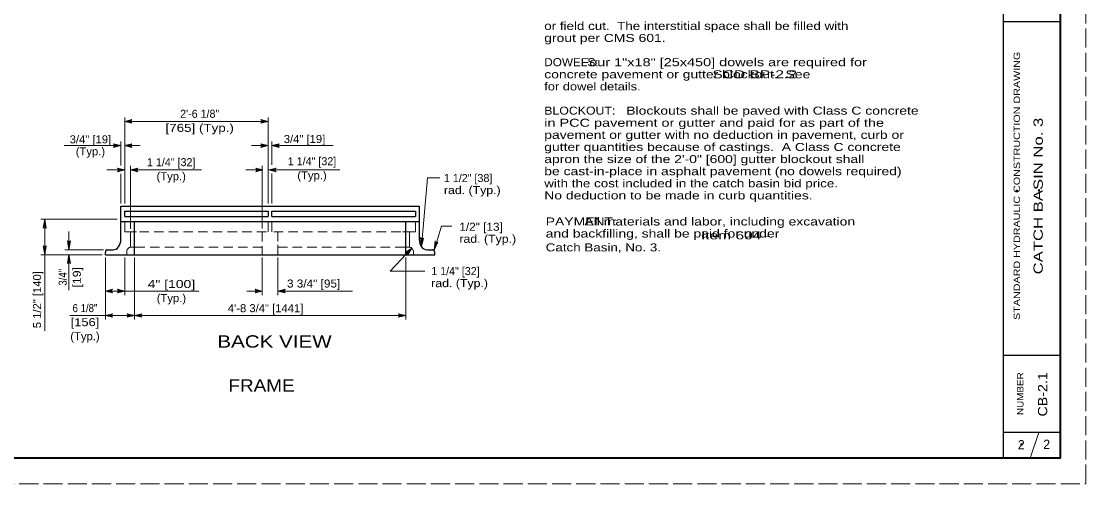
# Model space of a CAD drawing. Extents: x 1352.5 to 1386.5, y 735.9 to 779.9.
# Drawn here: x 1365.77 to 1386.51, y 735.92 to 744.93 of the extents above; entities that cross this region are included whole.
import ezdxf
from ezdxf.enums import TextEntityAlignment as Align

# ---------------------------------------------------------------- set-up
doc = ezdxf.new("R2010")
doc.units = 0
doc.header["$LTSCALE"] = 0.062
doc.header["$PDMODE"] = 32
doc.header["$PDSIZE"] = 0.031
doc.linetypes.add('LONG_DASHED', pattern=[7.5, 6, -1.5])
doc.linetypes.add('MEDIUM_DASHED', pattern=[4.5, 3, -1.5])
doc.layers.add('1', color=7, linetype='Continuous', lineweight=13)

msp = doc.modelspace()

# ---------------------------------------------------------------- linework, layer by layer
at = {"layer": '1', "lineweight": 25}
for p, q in [((1384.913, 736.41967), (1384.913, 757.41967)), ((1386.013, 757.41967), (1386.013, 736.41967)), ((1386.013, 744.91967), (1384.913, 744.91967)), ((1367.78425, 741.12625), (1367.78425, 741.22617)), ((1367.78425, 741.22617), (1370.5785, 741.22617)), ((1370.5785, 741.22617), (1370.5785, 741.12625)), ((1370.654, 741.22617), (1373.44825, 741.22617)), ((1370.654, 741.12625), (1370.654, 741.22617)), ((1373.44825, 741.22617), (1373.44825, 741.12625)), ((1367.70875, 741.02633), (1373.52375, 741.02633)), ((1367.78425, 741.12625), (1370.5785, 741.12625)), ((1367.973, 740.37667), (1367.973, 741.02633)), ((1370.654, 741.12625), (1373.44825, 741.12625)), ((1373.25942, 740.37667), (1373.25942, 741.02633)), ((1367.40667, 740.37667), (1367.40667, 740.42667)), ((1367.44442, 740.47667), (1367.55767, 740.47667)), ((1373.67475, 740.47667), (1373.78808, 740.47667)), ((1373.82583, 740.37667), (1373.82583, 740.42667)), ((1367.40667, 740.37667), (1373.82583, 740.37667)), ((1386.013, 738.41967), (1384.913, 738.41967)), ((1386.013, 736.91967), (1384.913, 736.91967))]:
    msp.add_line(p, q, dxfattribs=at)
at = {"layer": '1'}
for p, q in [((1367.78425, 741.37608), (1367.78425, 743.05675)), ((1367.91242, 743.0005), (1367.78425, 742.97808)), ((1367.90808, 742.98942), (1367.78425, 742.97808)), ((1367.78425, 742.97808), (1370.5785, 742.97808)), ((1367.90675, 742.97808), (1367.78425, 742.97808)), ((1367.909, 742.96367), (1367.78425, 742.97808)), ((1367.91392, 742.95333), (1367.78425, 742.97808)), ((1370.44875, 742.95333), (1370.5785, 742.97808)), ((1370.45025, 743.0005), (1370.5785, 742.97808)), ((1370.45367, 742.96367), (1370.5785, 742.97808)), ((1370.45458, 742.98942), (1370.5785, 742.97808)), ((1370.45592, 742.97808), (1370.5785, 742.97808)), ((1370.5785, 741.37608), (1370.5785, 743.05675)), ((1367.70658, 742.50733), (1366.60142, 742.50733)), ((1367.57692, 742.48258), (1367.70658, 742.50733)), ((1367.57842, 742.52975), (1367.70658, 742.50733)), ((1367.58183, 742.493), (1367.70658, 742.50733)), ((1367.58275, 742.51867), (1367.70658, 742.50733)), ((1367.58408, 742.50733), (1367.70658, 742.50733)), ((1367.70875, 742.11583), (1367.70875, 742.586)), ((1367.91033, 742.52975), (1367.78217, 742.50733)), ((1367.906, 742.51867), (1367.78217, 742.50733)), ((1367.90467, 742.50733), (1367.78217, 742.50733)), ((1367.90692, 742.493), (1367.78217, 742.50733)), ((1367.91183, 742.48258), (1367.78217, 742.50733)), ((1367.78217, 742.50733), (1368.08525, 742.50733)), ((1370.57858, 742.50733), (1370.25658, 742.50733)), ((1370.44892, 742.48258), (1370.57858, 742.50733)), ((1370.45042, 742.52975), (1370.57858, 742.50733)), ((1370.45383, 742.493), (1370.57858, 742.50733)), ((1370.45475, 742.51867), (1370.57858, 742.50733)), ((1370.45608, 742.50733), (1370.57858, 742.50733)), ((1370.654, 742.1345), (1370.654, 742.586)), ((1370.78233, 742.52975), (1370.65408, 742.50733)), ((1370.778, 742.51867), (1370.65408, 742.50733)), ((1370.65408, 742.50733), (1371.84508, 742.50733)), ((1370.77667, 742.50733), (1370.65408, 742.50733)), ((1370.77892, 742.493), (1370.65408, 742.50733)), ((1370.78383, 742.48258), (1370.65408, 742.50733)), ((1367.656, 742.05442), (1367.78425, 742.032)), ((1367.66042, 742.04333), (1367.78425, 742.032)), ((1367.8975, 740.88758), (1367.8975, 742.11067)), ((1368.02567, 742.05442), (1367.8975, 742.032)), ((1368.02133, 742.04333), (1367.8975, 742.032)), ((1370.34967, 742.05442), (1370.47783, 742.032)), ((1370.354, 742.04333), (1370.47783, 742.032)), ((1370.46517, 740.89475), (1370.46517, 742.11067)), ((1370.71933, 742.05442), (1370.59117, 742.032)), ((1370.715, 742.04333), (1370.59117, 742.032)), ((1367.78425, 742.032), (1367.43425, 742.032)), ((1367.6545, 742.00717), (1367.78425, 742.032)), ((1367.65942, 742.01758), (1367.78425, 742.032)), ((1367.66167, 742.032), (1367.78425, 742.032)), ((1367.70875, 741.37608), (1367.70875, 741.95742)), ((1368.02008, 742.032), (1367.8975, 742.032)), ((1368.02233, 742.01758), (1367.8975, 742.032)), ((1368.02725, 742.00717), (1367.8975, 742.032)), ((1367.8975, 742.032), (1369.27792, 742.032)), ((1370.47783, 742.032), (1370.14525, 742.032)), ((1370.34817, 742.00717), (1370.47783, 742.032)), ((1370.35308, 742.01758), (1370.47783, 742.032)), ((1370.35533, 742.032), (1370.47783, 742.032)), ((1370.71367, 742.032), (1370.59117, 742.032)), ((1370.71592, 742.01758), (1370.59117, 742.032)), ((1370.72083, 742.00717), (1370.59117, 742.032)), ((1370.59117, 742.032), (1371.97675, 742.032)), ((1370.654, 741.37608), (1370.654, 741.96208)), ((1366.20492, 740.91417), (1366.22475, 741.07625)), ((1366.21325, 740.92025), (1366.22475, 741.07625)), ((1366.22475, 740.92308), (1366.22475, 741.07625)), ((1366.23383, 740.9215), (1366.22475, 741.07625)), ((1366.24267, 740.91608), (1366.22475, 741.07625)), ((1367.78425, 741.02633), (1367.78425, 740.82642)), ((1373.44825, 741.02633), (1373.44825, 740.82642)), ((1366.69683, 740.47667), (1366.69683, 740.8345)), ((1367.78425, 740.82642), (1368.01508, 740.82642)), ((1367.8975, 740.82642), (1367.8975, 740.52658)), ((1373.44825, 740.82642), (1373.19692, 740.82642)), ((1373.33492, 740.82642), (1373.33492, 740.52658)), ((1366.67892, 740.63683), (1366.69683, 740.47667)), ((1366.68775, 740.63142), (1366.69683, 740.47667)), ((1366.71667, 740.63875), (1366.69683, 740.47667)), ((1366.70833, 740.63258), (1366.69683, 740.47667)), ((1366.69683, 740.62975), (1366.69683, 740.47667)), ((1373.56075, 740.70067), (1373.5695, 740.54117)), ((1373.56942, 740.6935), (1373.5695, 740.54117)), ((1373.59925, 740.69392), (1373.5695, 740.54117)), ((1373.59042, 740.68983), (1373.5695, 740.54117)), ((1373.5785, 740.68975), (1373.5695, 740.54117)), ((1373.84117, 740.62942), (1373.81217, 740.47092)), ((1373.84792, 740.62067), (1373.81217, 740.47092)), ((1373.877, 740.61567), (1373.81217, 740.47092)), ((1373.85592, 740.61533), (1373.81217, 740.47092)), ((1373.8675, 740.61325), (1373.81217, 740.47092)), ((1366.20683, 740.53692), (1366.22475, 740.37667)), ((1366.21567, 740.5315), (1366.22475, 740.37667)), ((1366.24458, 740.53883), (1366.22475, 740.37667)), ((1366.23625, 740.53267), (1366.22475, 740.37667)), ((1366.22475, 740.52983), (1366.22475, 740.37667)), ((1367.36883, 740.47667), (1366.61817, 740.47667)), ((1366.67892, 740.22633), (1366.69683, 740.38658)), ((1366.68775, 740.23175), (1366.69683, 740.38658)), ((1366.69683, 740.38658), (1366.69683, 739.69017)), ((1366.69683, 740.23342), (1366.69683, 740.38658)), ((1366.70833, 740.23058), (1366.69683, 740.38658)), ((1366.71667, 740.22442), (1366.69683, 740.38658)), ((1367.8975, 740.52658), (1368.01808, 740.52658)), ((1373.375, 740.50408), (1372.95808, 740.0575)), ((1373.33492, 740.52658), (1373.19275, 740.52658)), ((1373.27042, 740.42675), (1373.375, 740.50408)), ((1373.28142, 740.42225), (1373.375, 740.50408)), ((1373.2905, 740.41533), (1373.375, 740.50408)), ((1373.29942, 740.40375), (1373.375, 740.50408)), ((1373.30358, 740.39308), (1373.375, 740.50408)), ((1367.34283, 740.37667), (1366.14608, 740.37667)), ((1366.25183, 740.37667), (1366.187, 740.37667)), ((1367.40667, 739.11792), (1367.40667, 740.32675)), ((1367.78425, 739.5925), (1367.78425, 740.32675)), ((1370.46517, 739.5925), (1370.46517, 740.32675)), ((1370.76725, 739.5925), (1370.76725, 740.32675)), ((1372.95808, 740.0575), (1373.63017, 740.0575)), ((1367.53442, 739.69633), (1367.40617, 739.67392)), ((1367.53008, 739.68525), (1367.40617, 739.67392)), ((1367.52875, 739.67392), (1367.40617, 739.67392)), ((1367.531, 739.6595), (1367.40617, 739.67392)), ((1367.53592, 739.64917), (1367.40617, 739.67392)), ((1367.40667, 739.67117), (1369.22817, 739.67117)), ((1367.6545, 739.64633), (1367.78425, 739.67117)), ((1367.656, 739.69358), (1367.78425, 739.67117)), ((1367.65942, 739.65675), (1367.78425, 739.67117)), ((1367.66042, 739.6825), (1367.78425, 739.67117)), ((1367.66167, 739.67117), (1367.78425, 739.67117)), ((1370.46517, 739.67117), (1370.16308, 739.67117)), ((1370.3355, 739.64633), (1370.46517, 739.67117)), ((1370.337, 739.69358), (1370.46517, 739.67117)), ((1370.34042, 739.65675), (1370.46517, 739.67117)), ((1370.34133, 739.6825), (1370.46517, 739.67117)), ((1370.34267, 739.67117), (1370.46517, 739.67117)), ((1370.8955, 739.69358), (1370.76725, 739.67117)), ((1370.89108, 739.6825), (1370.76725, 739.67117)), ((1370.76725, 739.67117), (1372.22558, 739.67117)), ((1370.88983, 739.67117), (1370.76725, 739.67117)), ((1370.89208, 739.65675), (1370.76725, 739.67117)), ((1370.897, 739.64633), (1370.76725, 739.67117)), ((1367.53483, 739.219), (1367.40667, 739.19658)), ((1367.5305, 739.20792), (1367.40667, 739.19658)), ((1367.52917, 739.19658), (1367.40667, 739.19658)), ((1367.53142, 739.18217), (1367.40667, 739.19658)), ((1367.53633, 739.17183), (1367.40667, 739.19658)), ((1367.84333, 739.17183), (1367.973, 739.19658)), ((1367.84483, 739.219), (1367.973, 739.19658)), ((1367.84825, 739.18217), (1367.973, 739.19658)), ((1367.84917, 739.20792), (1367.973, 739.19658)), ((1367.8505, 739.19658), (1367.973, 739.19658)), ((1368.10125, 739.219), (1367.973, 739.19658)), ((1368.09692, 739.20792), (1367.973, 739.19658)), ((1367.973, 739.19658), (1371.11825, 739.19658)), ((1368.09558, 739.19658), (1367.973, 739.19658)), ((1368.09783, 739.18217), (1367.973, 739.19658)), ((1368.10275, 739.17183), (1367.973, 739.19658)), ((1371.11825, 739.19658), (1373.25942, 739.19658)), ((1373.12975, 739.17183), (1373.25942, 739.19658)), ((1373.13125, 739.219), (1373.25942, 739.19658)), ((1373.13467, 739.18217), (1373.25942, 739.19658)), ((1373.13558, 739.20792), (1373.25942, 739.19658)), ((1373.13692, 739.19658), (1373.25942, 739.19658)), ((1385.42967, 736.41967), (1385.59633, 736.91967))]:
    msp.add_line(p, q, dxfattribs=at)
at = {"layer": '1', "linetype": 'MEDIUM_DASHED'}
for p, q in [((1367.8975, 740.82642), (1367.8975, 740.52658)), ((1370.46517, 740.82642), (1370.46517, 740.52658)), ((1373.33492, 740.82642), (1373.33492, 740.52658)), ((1367.822, 740.42667), (1367.822, 740.37667)), ((1370.46517, 740.52658), (1367.8975, 740.52658)), ((1370.46517, 740.55042), (1370.46517, 740.37667)), ((1370.76725, 740.52658), (1373.33492, 740.52658)), ((1373.4105, 740.42667), (1373.4105, 740.37667))]:
    msp.add_line(p, q, dxfattribs=at)
at = {"layer": '1', "linetype": 'LONG_DASHED'}
msp.add_lwpolyline([(1352.513, 735.91967), (1386.513, 735.91967), (1386.513, 757.91967), (1352.513, 757.91967)], close=True, dxfattribs=at)
at = {"layer": '1', "lineweight": 25}
for points in [[(1386.013, 736.41967), (1354.513, 736.41967), (1354.513, 757.41967)], [(1367.70875, 740.6765), (1367.70875, 741.32617), (1373.52375, 741.32617), (1373.52375, 740.6765)]]:
    msp.add_lwpolyline(points, dxfattribs=at)
at = {"layer": '1', "lineweight": 40}
msp.add_lwpolyline([(1354.513, 757.41967), (1386.013, 757.41967), (1386.013, 736.41967), (1354.513, 736.41967)], close=True, dxfattribs=at)
msp.add_lwpolyline([(1354.513, 757.41967), (1386.013, 757.41967), (1386.013, 736.41967), (1354.513, 736.41967)], close=True, dxfattribs=at)
at = {"layer": '1'}
for points in [[(1367.92583, 742.94267), (1367.78425, 742.97808), (1367.92583, 743.0135)], [(1370.43683, 742.94267), (1370.5785, 742.97808), (1370.43683, 743.0135)], [(1367.565, 742.472), (1367.70658, 742.50733), (1367.565, 742.54275)], [(1367.92375, 742.472), (1367.78217, 742.50733), (1367.92375, 742.54275)], [(1370.437, 742.472), (1370.57858, 742.50733), (1370.437, 742.54275)], [(1370.79575, 742.472), (1370.65408, 742.50733), (1370.79575, 742.54275)], [(1367.64267, 741.99658), (1367.78425, 742.032), (1367.64267, 742.06742)], [(1368.03908, 741.99658), (1367.8975, 742.032), (1368.03908, 742.06742)], [(1370.33625, 741.99658), (1370.47783, 742.032), (1370.33625, 742.06742)], [(1370.73275, 741.99658), (1370.59117, 742.032), (1370.73275, 742.06742)], [(1373.5695, 740.54117), (1373.68192, 741.87617), (1373.9245, 741.87617)], [(1367.638, 741.07625), (1367.55292, 741.07625), (1366.14608, 741.07625)], [(1366.19642, 740.89925), (1366.22475, 741.07625), (1366.25308, 740.89925)], [(1366.22475, 738.89967), (1366.22475, 740.84583), (1366.22475, 741.07625)], [(1373.81217, 740.47092), (1373.95533, 740.93575), (1374.15992, 740.93575)], [(1366.72517, 740.65367), (1366.69683, 740.47667), (1366.6685, 740.65367)], [(1373.60875, 740.70642), (1373.5695, 740.54117), (1373.55108, 740.71942)], [(1373.88917, 740.62617), (1373.81217, 740.47092), (1373.83617, 740.6495)], [(1366.25308, 740.55367), (1366.22475, 740.37667), (1366.19642, 740.55367)], [(1366.72517, 740.20958), (1366.69683, 740.38658), (1366.6685, 740.20958)], [(1373.303, 740.37717), (1373.375, 740.50408), (1373.25175, 740.42592)], [(1367.973, 739.11792), (1367.973, 739.62492), (1367.973, 740.32675)], [(1373.25942, 739.11792), (1373.25942, 740.12192), (1373.25942, 740.32675)], [(1367.54783, 739.6385), (1367.40617, 739.67392), (1367.54783, 739.70933)], [(1367.64267, 739.63575), (1367.78425, 739.67117), (1367.64267, 739.70658)], [(1370.32358, 739.63575), (1370.46517, 739.67117), (1370.32358, 739.70658)], [(1370.90883, 739.63575), (1370.76725, 739.67117), (1370.90883, 739.70658)], [(1366.71308, 739.19658), (1367.83292, 739.19658), (1367.973, 739.19658)], [(1367.54825, 739.16117), (1367.40667, 739.19658), (1367.54825, 739.232)], [(1367.83142, 739.16117), (1367.973, 739.19658), (1367.83142, 739.232)], [(1368.11467, 739.16117), (1367.973, 739.19658), (1368.11467, 739.232)], [(1373.11783, 739.16117), (1373.25942, 739.19658), (1373.11783, 739.232)]]:
    msp.add_lwpolyline(points, dxfattribs=at)
at = {"layer": '1', "linetype": 'MEDIUM_DASHED'}
for points in [[(1367.78425, 741.02633), (1367.78425, 740.82642), (1370.5785, 740.82642), (1370.5785, 741.02633)], [(1373.44825, 741.02633), (1373.44825, 740.82642), (1370.654, 740.82642), (1370.654, 741.02633)], [(1370.76725, 740.82642), (1370.76725, 740.57367), (1370.76725, 740.37667)]]:
    msp.add_lwpolyline(points, dxfattribs=at)
at = {"layer": '1'}
for centre, major_axis, ratio, start_param, end_param in [((1367.93727, 742.97813), (0, 0.0382), 0.8, 0.38550522, 2.75611836), ((1370.42544, 742.97813), (0, 0.0382), 0.8, 3.52706694, 5.89768008), ((1367.55357, 742.5074), (0, 0.0382), 0.8, 3.52706694, 5.89768008), ((1367.93516, 742.5074), (0, 0.0382), 0.8, 0.38550522, 2.75611836), ((1370.42556, 742.5074), (0, 0.0382), 0.8, 3.52706694, 5.89768008), ((1370.80715, 742.5074), (0, 0.0382), 0.8, 0.38550522, 2.75611836), ((1367.6312, 742.03201), (0, 0.0382), 0.8, 3.52706694, 5.89768008), ((1368.05055, 742.03201), (0, 0.0382), 0.8, 0.38550522, 2.75611836), ((1370.32483, 742.03201), (0, 0.0382), 0.8, 3.52706694, 5.89768008), ((1370.74418, 742.03201), (0, 0.0382), 0.8, 0.38550522, 2.75611836), ((1366.22476, 740.88499), (0, 0.0382), 0.8, 5.0978942, 7.46850734), ((1366.69679, 740.66792), (0, -0.0382), 0.8, 5.0978942, 7.46850734), ((1367.55767, 740.67651), (0, 0.19988), 0.755635, 4.68770266, 4.71238898), ((1373.58074, 740.72675), (-0.01013, 0.03684), 0.8, 1.55294903, 3.92356217), ((1373.86675, 740.65134), (-0.00239, -0.03813), 0.8, 4.81159476, 7.1822079), ((1366.2247, 740.56798), (0, -0.0382), 0.8, 5.0978942, 7.46850734), ((1367.89751, 740.42666), (0, 0.09994), 0.755635, 0, 1.57079633), ((1373.26948, 740.39329), (-0.02767, 0.02634), 0.8, 3.52706694, 5.89768008), ((1373.33495, 740.42666), (0, 0.09994), 0.755635, 4.71238898, 6.28318531), ((1366.69679, 740.19527), (0, 0.0382), 0.8, 5.09786327, 7.46847641), ((1367.55923, 739.67398), (0, 0.0382), 0.8, 0.38550522, 2.75611836), ((1367.63119, 739.67118), (0, 0.0382), 0.8, 3.52706694, 5.89768008), ((1370.31216, 739.67118), (0, 0.0382), 0.8, 3.52706694, 5.89768008), ((1370.92031, 739.67118), (0, 0.0382), 0.8, 0.38550522, 2.75611836), ((1367.55967, 739.19663), (0, 0.0382), 0.8, 0.38550522, 2.75611836), ((1367.82, 739.19663), (0, 0.0382), 0.8, 3.52706694, 5.89768008), ((1368.12607, 739.19663), (0, 0.0382), 0.8, 0.38550522, 2.75611836), ((1373.1064, 739.19663), (0, 0.0382), 0.8, 3.52706694, 5.89768008)]:
    msp.add_ellipse(centre, major_axis=major_axis, ratio=ratio, start_param=start_param, end_param=end_param, dxfattribs=at)
at = {"layer": '1', "lineweight": 25}
for centre, major_axis, start_param, end_param in [((1367.55767, 740.67651), (0, 0.19988), 3.14159265, 4.71238898), ((1373.67479, 740.67651), (0, 0.19988), 1.57079633, 3.14159265), ((1367.44439, 740.42666), (0, 0.04997), 0, 1.57079633), ((1373.78807, 740.42666), (0, 0.04997), 4.71238898, 6.28318531)]:
    msp.add_ellipse(centre, major_axis=major_axis, ratio=0.755635, start_param=start_param, end_param=end_param, dxfattribs=at)
at = {"layer": '1'}
for p in [(1385.17042, 741.62567), (1385.60325, 741.633), (1385.26108, 736.68342)]:
    msp.add_point(p, dxfattribs=at)

# ---------------------------------------------------------------- texts
for s, height, width, p in [('or field cut.  The interstitial space shall be filled with', 0.156, 1.25, (1375.96008, 744.7605)), ('grout per CMS 601.', 0.156, 1.3, (1375.96008, 744.52583)), ('DOWELS:', 0.156, 1.1, (1375.96008, 744.05383)), ('         Four 1"x18" [25x450] dowels are required for', 0.156, 1.35, (1375.96008, 744.05383)), ('concrete pavement or gutter blockout.  See', 0.156, 1.3, (1375.96008, 743.81783)), ('                                       SCD BP-2.2 ', 0.156, 1.45, (1375.96008, 743.81783)), ('for dowel details.', 0.156, 1.2, (1375.96008, 743.58183)), ('BLOCKOUT:', 0.156, 1.15, (1375.96008, 743.10983)), ('Blockouts shall be paved with Class C concrete', 0.156, 1.3, (1377.559, 743.10983)), ('in PCC pavement or gutter and paid for as part of the', 0.156, 1.35, (1375.96008, 742.87383)), ('3/4" [19]', 0.156, 1.05, (1370.88392, 742.55733)), ('pavement or gutter with no deduction in pavement, curb or', 0.156, 1.3, (1375.96008, 742.63783)), ('gutter quantities because of castings.  A Class C concrete', 0.156, 1.3, (1375.96008, 742.40183)), ('apron the size of the 2\'-0" [600] gutter blockout shall', 0.156, 1.3, (1375.96008, 742.16583)), ('be cast-in-place in asphalt pavement (no dowels required)', 0.156, 1.3, (1375.96008, 741.92983)), ('with the cost included in the catch basin bid price.', 0.156, 1.25, (1375.96008, 741.69383)), ('rad. (Typ.)', 0.156, 1.15, (1374.00475, 741.56183)), ('No deduction to be made in curb quantities.', 0.156, 1.3, (1375.96008, 741.45783)), ('1/2" [13]', 0.156, 1.1, (1374.30575, 740.84758)), ('PAYMENT: ', 0.156, 1.3, (1375.98908, 740.95008)), ('          All materials and labor, including excavation', 0.156, 1.3, (1375.98908, 740.95008)), ('and backfilling, shall be paid for under ', 0.156, 1.3, (1375.98908, 740.71608)), ('                                    Item 604 - ', 0.156, 1.45, (1375.98917, 740.67942)), ('rad. (Typ.)', 0.156, 1.15, (1374.30575, 740.61292)), ('Catch Basin, No. 3.', 0.156, 1.25, (1375.98917, 740.44542)), ('3 3/4" [95]', 0.156, 1.1, (1370.94642, 739.7415)), ('rad. (Typ.)', 0.156, 1.15, (1373.75742, 739.74875)), ('4\'-8 3/4" [1441]', 0.156, 1.05, (1369.79425, 739.26142)), ('BACK VIEW', 0.24, 1.25, (1369.58892, 738.57125)), ('FRAME', 0.24, 1.15, (1369.80458, 737.71392))]:
    msp.add_text(s, height=height, dxfattribs=dict(at, width=width)).set_placement(p)
for s, height, width, p in [('STANDARD HYDRAULIC CONSTRUCTION DRAWING', 0.125, 1.25, (1385.23292, 741.72371)), ('CATCH BASIN No. 3', 0.18, 1.35, (1385.67617, 741.52396)), ('3/4"', 0.156, 0.9, (1366.65367, 739.94192)), ('[19]', 0.156, 1.15, (1366.92767, 739.94187)), ('NUMBER', 0.125, 1.15, (1385.3, 737.67375)), ('CB-2.1', 0.18, 1.15, (1385.76233, 737.66004))]:
    msp.add_text(s, height=height, rotation=90, dxfattribs=dict(at, width=width)).set_placement(p, align=Align.CENTER)
for s, height, p in [('2\'-6 1/8"', 0.156, (1369.24521, 743.04833)), ('1 1/4" [32]', 0.156, (1368.68988, 742.10558)), ('1 1/4" [32]', 0.156, (1371.43421, 742.12392)), ('2', 0.18, (1385.25746, 736.58975)), ('2', 0.18, (1385.75221, 736.59633))]:
    msp.add_text(s, height=height, dxfattribs=at).set_placement(p, align=Align.CENTER)
for s, width, p in [('[765] (Typ.)', 1.25, (1369.24525, 742.77433)), ('3/4" [19]', 1.05, (1367.11567, 742.55092)), ('(Typ.)', 1.05, (1367.11571, 742.31625)), ('(Typ.)', 1.05, (1368.68996, 741.83158)), ('(Typ.)', 1.05, (1371.43429, 741.84992)), ('4" [100]', 1.3, (1368.69417, 739.732)), ('(Typ.)', 1.05, (1368.69421, 739.458)), ('6 1/8"', 0.9, (1367.00937, 739.26258)), ('[156]', 1.2, (1367.00942, 738.98858)), ('(Typ.)', 1.05, (1367.00946, 738.71458))]:
    msp.add_text(s, height=0.156, dxfattribs=dict(at, width=width)).set_placement(p, align=Align.CENTER)
for s, p in [('1 1/2" [38]', (1374.00475, 741.7965)), ('1 1/4" [32]', (1373.75742, 739.98342))]:
    msp.add_text(s, height=0.156, dxfattribs=at).set_placement(p)
at = {"layer": '1', "width": 1.05}
msp.add_text('5 1/2" [140]', height=0.156, rotation=90, dxfattribs=at).set_placement((1366.15342, 738.94833))

doc.saveas('drawing.dxf')
